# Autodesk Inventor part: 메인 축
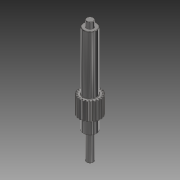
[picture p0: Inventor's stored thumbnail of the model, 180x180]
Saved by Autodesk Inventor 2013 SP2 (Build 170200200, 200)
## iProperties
Created: 2016-02
Part Number: 메인 축
Material: 강철, 연강
Document SubType Name: Modeling
Categories: <?xml version="1.0" encoding="UTF-16"?> <MemberInstance><Categories><FamilyTemplate><FamilyTemplateParameter ValueType="xs:double" Id="1" ObjectReferenceKey="da
Density: 7.86 g/cm^3
Mass: 187.503 g
Surface Area: 82.0529 cm^2
Volume: 23.8554 cm^3
Author: mdu
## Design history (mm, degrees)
sketch "Sketch1"
  geometry: C1 r 12 at (0, 0)
  constraints: 1 centre point
  dimensions: "d0" = 24 diameter of C1 (= da_da)
extrude "Extrusion1" new body sketch "Sketch1" distance "d1" = 20 (= da_b); taper "d2" = 0 deg
workplane "Work Plane2"
feature "피치 지름" dims "d4" = 10, "d5" = 0
workplane "Work Plane8"
workplane "Work Plane9"
chamfer "모따기1" distance "d49" = 0.2; stored, may be unused: second distance "d50" = 2, angle "d51" = 45 deg
sketch "스케치3"
  geometry: C1 r 7.5 at (0, 0); 1 further point
  constraints: 1 centre point, 1 coincident
  dimensions: "d52" = 15 diameter of C1
extrude "돌출2" join sketch "스케치3" distance "d53" = 66; taper "d54" = 0 deg
sketch "스케치4"
  geometry: C1 r 4 at (0, 0); 1 further point
  constraints: 1 centre point, 1 coincident
  dimensions: "d55" = 8 diameter of C1
extrude "돌출3" join sketch "스케치4" distance "d56" = 7; taper "d57" = 0 deg
sketch "스케치5"
  geometry: C1 r 7.5 at (0, 0) reference; C2 r 7.5 at (0, 0) reference; 1 further point
extrude "돌출4" join sketch "스케치5" distance "d62" = 16; taper "d63" = 0 deg
sketch "스케치6"
  geometry: C1 r 4 at (0, 0); 1 further point
  constraints: 1 centre point, 1 coincident
  dimensions: "d64" = 8 diameter of C1
extrude "돌출5" join sketch "스케치6" distance "d65" = 30; taper "d66" = 0 deg
chamfer "모따기2" distance "d58" = 0.5; stored, may be unused: second distance "d59" = 2, angle "d60" = 45 deg
fillet "모깎기1" dims "d61" = 0.5
feature "스퍼 기어" dims "da_b" = 20, "da_d" = 22, "da_aw" = 31, "da_da" = 24, "da_df" = 19.5, "da_dw" = 22, angle "da_beta" = 0 deg, "da_lefttooth" = 0, "da_righttooth" = 0
sketch "스케치7" dims "d68" = 18
  geometry: C1 r 0.25 at (0, -9); 2 further points
  constraints: 2 vertical alignment, 1 centre point, 1 coincident, 2 other
  dimensions: "d67" = 0.5 diameter of C1
extrude "돌출6" join sketch "스케치7" distance "d69" = 0.3; taper "d70" = 0 deg
body "Solid1"
sketch "Sketch2"
  geometry: C1 r 12 at (0, 0) reference; C2 r 11 at (0, 0)
  constraints: 1 centre point, 1 coincident
  dimensions: "d3" = 22 diameter of C2 (= da_dw)
body "Srf1"
node "투영된 루프1"
other parameters: "d16" = 31 (= da_aw), "d17" = 0, "d34" = 1.428 (computed from da_z), "d39" = 0, "d41" = 0, "d43" = 31 (= da_aw), "d46" = 31 (= da_aw), "d47" = 0, "d48" = 0
